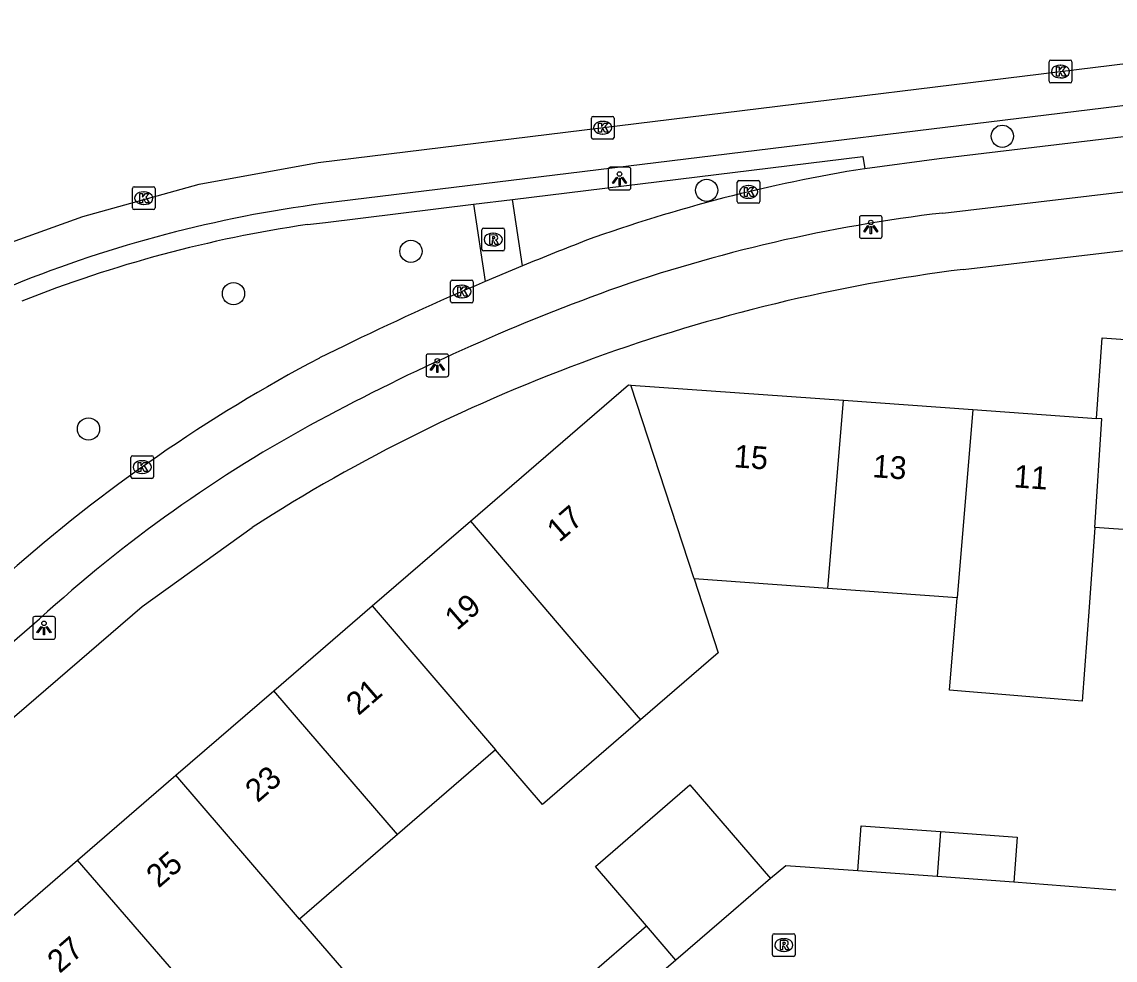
# Model space of a CAD drawing. Extents: x 160304 to 160954, y 383686 to 384161.
# Drawn here: x 160430.67 to 160478.74, y 384109.32 to 384150.58 of the extents above; entities that cross this region are included whole.
import ezdxf

# ---------------------------------------------------------------- set-up
doc = ezdxf.new("R2010")
doc.units = 0
for name, color, linetype in [('IMGEO_Berm_open', 7, 'Continuous'), ('IMGEO_Boom', 7, 'Continuous'), ('IMGEO_Fietspad_open', 7, 'Continuous'), ('IMGEO_Kolk', 7, 'Continuous'), ('IMGEO_Lichtpunt', 7, 'Continuous'), ('IMGEO_Pand', 7, 'Continuous'), ('IMGEO_Pand_nummerreeks', 7, 'Continuous'), ('IMGEO_Parkeervlak_open', 7, 'Continuous'), ('IMGEO_Rijbaan_lokaal_gesloten', 7, 'Continuous'), ('IMGEO_Rijbaan_lokaal_open', 7, 'Continuous'), ('IMGEO_Rioolput', 7, 'Continuous'), ('IMGEO_Voetpad_open', 7, 'Continuous')]:
    doc.layers.add(name, color=color, linetype=linetype)

msp = doc.modelspace()

# ---------------------------------------------------------------- linework, layer by layer
at = {"layer": 'IMGEO_Berm_open'}
for points in [[(160452.244, 384142.771), (160467.646, 384144.661), (160467.726, 384144.119)], [(160443.227, 384141.665), (160444.02, 384141.762), (160450.53, 384142.561)]]:
    msp.add_lwpolyline(points, dxfattribs=at)
msp.add_arc((160451.295, 384086.519), 55.733, 98.3238, 111.7235, dxfattribs=at)
at = {"layer": 'IMGEO_Boom'}
for centre in [(160473.778, 384145.548), (160460.776, 384143.172), (160447.773, 384140.487), (160439.974, 384138.628), (160433.596, 384132.677)]:
    msp.add_circle(centre, 0.489, dxfattribs=at)
at = {"layer": 'IMGEO_Fietspad_open'}
for points in [[(160500.935, 384148.123), (160500, 384148.012), (160470.995, 384144.557), (160467.726, 384144.119)], [(160471.168, 384142.172), (160500, 384145.577), (160501.724, 384145.785)], [(160452.675, 384139.848), (160451.032, 384139.16)], [(160444.823, 384136.323), (160443.757, 384135.797)], [(160420.593, 384114.949), (160431.449, 384124.329)]]:
    msp.add_lwpolyline(points, dxfattribs=at)
for centre, radius, start, end in [((160478.287, 384077.742), 67.212, 99.04077, 109.82387), ((160479.052, 384074.745), 67.886, 96.66896, 109.40242), ((160500.424, 384024.085), 125.224, 111.02655, 112.41499), ((160505.161, 384012.481), 137.759, 113.13674, 115.97623), ((160490.056, 384046.815), 97.892, 110.04653, 118.24507), ((160476.283, 384074.16), 69.692, 117.82068, 131.53435), ((160472.85, 384079.044), 61.358, 118.33433, 132.43502)]:
    msp.add_arc(centre, radius, start, end, dxfattribs=at)
at = {"layer": 'IMGEO_Kolk'}
for p, q in [((160475.835, 384147.967), (160475.835, 384148.819)), ((160475.91, 384148.893), (160476.762, 384148.893)), ((160476.323, 384148.673), (160476.348, 384148.673)), ((160476.836, 384148.819), (160476.836, 384147.967)), ((160476.346, 384148.113), (160476.321, 384148.113)), ((160476.762, 384147.893), (160475.91, 384147.893)), ((160455.707, 384145.496), (160455.707, 384146.348)), ((160455.782, 384146.422), (160456.634, 384146.422)), ((160456.195, 384146.202), (160456.22, 384146.202)), ((160456.708, 384146.348), (160456.708, 384145.496)), ((160456.634, 384145.422), (160455.782, 384145.422)), ((160456.218, 384145.642), (160456.193, 384145.642)), ((160435.526, 384142.399), (160435.526, 384143.251)), ((160435.601, 384143.325), (160436.453, 384143.325)), ((160436.527, 384143.251), (160436.527, 384142.399)), ((160462.121, 384142.675), (160462.121, 384143.527)), ((160462.196, 384143.601), (160463.048, 384143.601)), ((160462.609, 384143.381), (160462.634, 384143.381)), ((160463.122, 384143.527), (160463.122, 384142.675)), ((160436.014, 384143.105), (160436.039, 384143.105)), ((160462.632, 384142.821), (160462.607, 384142.821)), ((160436.453, 384142.325), (160435.601, 384142.325)), ((160436.037, 384142.545), (160436.012, 384142.545)), ((160463.048, 384142.601), (160462.196, 384142.601)), ((160449.516, 384138.295), (160449.516, 384139.147)), ((160449.591, 384139.221), (160450.443, 384139.221)), ((160450.004, 384139.001), (160450.029, 384139.001)), ((160450.517, 384139.147), (160450.517, 384138.295)), ((160450.443, 384138.221), (160449.591, 384138.221)), ((160450.027, 384138.441), (160450.002, 384138.441)), ((160435.458, 384130.574), (160435.458, 384131.426)), ((160435.533, 384131.5), (160436.385, 384131.5)), ((160435.946, 384131.28), (160435.971, 384131.28)), ((160436.459, 384131.426), (160436.459, 384130.574)), ((160436.385, 384130.5), (160435.533, 384130.5)), ((160435.969, 384130.72), (160435.944, 384130.72))]:
    msp.add_line(p, q, dxfattribs=at)
for points in [[(160475.835, 384147.967), (160475.835, 384148.819)], [(160475.91, 384148.893), (160476.762, 384148.893)], [(160476.156, 384148.593), (160476.279, 384148.593), (160476.279, 384148.442), (160476.409, 384148.593), (160476.573, 384148.593), (160476.427, 384148.442), (160476.58, 384148.193), (160476.428, 384148.193), (160476.343, 384148.357), (160476.279, 384148.29), (160476.279, 384148.193), (160476.156, 384148.193), (160476.156, 384148.593)], [(160476.836, 384148.819), (160476.836, 384147.967)], [(160476.762, 384147.893), (160475.91, 384147.893)], [(160455.707, 384145.496), (160455.707, 384146.348)], [(160455.782, 384146.422), (160456.634, 384146.422)], [(160456.708, 384146.348), (160456.708, 384145.496)], [(160456.028, 384146.122), (160456.151, 384146.122), (160456.151, 384145.971), (160456.281, 384146.122), (160456.445, 384146.122), (160456.299, 384145.971), (160456.452, 384145.722), (160456.3, 384145.722), (160456.215, 384145.886), (160456.151, 384145.819), (160456.151, 384145.722), (160456.028, 384145.722), (160456.028, 384146.122)], [(160456.634, 384145.422), (160455.782, 384145.422)], [(160435.526, 384142.399), (160435.526, 384143.251)], [(160435.601, 384143.325), (160436.453, 384143.325)], [(160436.527, 384143.251), (160436.527, 384142.399)], [(160462.121, 384142.675), (160462.121, 384143.527)], [(160462.196, 384143.601), (160463.048, 384143.601)], [(160462.442, 384143.301), (160462.565, 384143.301), (160462.565, 384143.15), (160462.695, 384143.301), (160462.859, 384143.301), (160462.713, 384143.15), (160462.866, 384142.901), (160462.714, 384142.901), (160462.629, 384143.065), (160462.565, 384142.998), (160462.565, 384142.901), (160462.442, 384142.901), (160462.442, 384143.301)], [(160463.122, 384143.527), (160463.122, 384142.675)], [(160435.847, 384143.025), (160435.97, 384143.025), (160435.97, 384142.874), (160436.1, 384143.025), (160436.264, 384143.025), (160436.118, 384142.874), (160436.271, 384142.625), (160436.119, 384142.625), (160436.034, 384142.789), (160435.97, 384142.722), (160435.97, 384142.625), (160435.847, 384142.625), (160435.847, 384143.025)], [(160436.453, 384142.325), (160435.601, 384142.325)], [(160463.048, 384142.601), (160462.196, 384142.601)], [(160449.516, 384138.295), (160449.516, 384139.147)], [(160449.591, 384139.221), (160450.443, 384139.221)], [(160450.517, 384139.147), (160450.517, 384138.295)], [(160449.837, 384138.921), (160449.96, 384138.921), (160449.96, 384138.77), (160450.09, 384138.921), (160450.254, 384138.921), (160450.108, 384138.77), (160450.261, 384138.521), (160450.109, 384138.521), (160450.024, 384138.685), (160449.96, 384138.618), (160449.96, 384138.521), (160449.837, 384138.521), (160449.837, 384138.921)], [(160450.443, 384138.221), (160449.591, 384138.221)], [(160435.458, 384130.574), (160435.458, 384131.426)], [(160435.533, 384131.5), (160436.385, 384131.5)], [(160436.459, 384131.426), (160436.459, 384130.574)], [(160435.779, 384131.2), (160435.902, 384131.2), (160435.902, 384131.049), (160436.032, 384131.2), (160436.196, 384131.2), (160436.05, 384131.049), (160436.203, 384130.8), (160436.051, 384130.8), (160435.966, 384130.964), (160435.902, 384130.897), (160435.902, 384130.8), (160435.779, 384130.8), (160435.779, 384131.2)], [(160436.385, 384130.5), (160435.533, 384130.5)]]:
    msp.add_lwpolyline(points, dxfattribs=at)
for centre, start, end in [((160475.912, 384148.817), 91.552, 178.448), ((160475.912, 384148.817), 91.552, 178.448), ((160476.76, 384148.817), 1.552, 88.448), ((160476.76, 384148.817), 1.552, 88.448), ((160475.912, 384147.969), 181.552, 268.448), ((160475.912, 384147.969), 181.552, 268.448), ((160476.76, 384147.969), 271.552, 358.448), ((160476.76, 384147.969), 271.552, 358.448), ((160455.784, 384146.346), 91.552, 178.448), ((160455.784, 384146.346), 91.552, 178.448), ((160456.632, 384146.346), 1.552, 88.448), ((160456.632, 384146.346), 1.552, 88.448), ((160455.784, 384145.498), 181.552, 268.448), ((160455.784, 384145.498), 181.552, 268.448), ((160456.632, 384145.498), 271.552, 358.448), ((160456.632, 384145.498), 271.552, 358.448), ((160435.603, 384143.249), 91.552, 178.448), ((160435.603, 384143.249), 91.552, 178.448), ((160436.451, 384143.249), 1.552, 88.448), ((160436.451, 384143.249), 1.552, 88.448), ((160462.198, 384143.525), 91.552, 178.448), ((160462.198, 384143.525), 91.552, 178.448), ((160463.046, 384143.525), 1.552, 88.448), ((160463.046, 384143.525), 1.552, 88.448), ((160435.603, 384142.401), 181.552, 268.448), ((160435.603, 384142.401), 181.552, 268.448), ((160436.451, 384142.401), 271.552, 358.448), ((160436.451, 384142.401), 271.552, 358.448), ((160462.198, 384142.677), 181.552, 268.448), ((160462.198, 384142.677), 181.552, 268.448), ((160463.046, 384142.677), 271.552, 358.448), ((160463.046, 384142.677), 271.552, 358.448), ((160449.593, 384139.145), 91.552, 178.448), ((160449.593, 384139.145), 91.552, 178.448), ((160450.441, 384139.145), 1.552, 88.448), ((160450.441, 384139.145), 1.552, 88.448), ((160449.593, 384138.297), 181.552, 268.448), ((160449.593, 384138.297), 181.552, 268.448), ((160450.441, 384138.297), 271.552, 358.448), ((160450.441, 384138.297), 271.552, 358.448), ((160435.535, 384131.424), 91.552, 178.448), ((160435.535, 384131.424), 91.552, 178.448), ((160436.383, 384131.424), 1.552, 88.448), ((160436.383, 384131.424), 1.552, 88.448), ((160435.535, 384130.576), 181.552, 268.448), ((160435.535, 384130.576), 181.552, 268.448), ((160436.383, 384130.576), 271.552, 358.448), ((160436.383, 384130.576), 271.552, 358.448)]:
    msp.add_arc(centre, 0.0765, start, end, dxfattribs=at)
for centre, major_axis, ratio, start_param, end_param in [((160476.322, 384148.393), (-0.387, 0.002), 0.722429, 4.712389, 7.853982), ((160476.347, 384148.393), (-0.39, 0.002), 0.717154, 1.570796, 4.712389), ((160456.194, 384145.922), (-0.387, 0.002), 0.722429, 4.712389, 7.853982), ((160456.219, 384145.922), (-0.39, 0.002), 0.717154, 1.570796, 4.712389), ((160462.608, 384143.101), (-0.387, 0.002), 0.722429, 4.712389, 7.853982), ((160462.633, 384143.101), (-0.39, 0.002), 0.717154, 1.570796, 4.712389), ((160436.013, 384142.825), (-0.387, 0.002), 0.722429, 4.712389, 7.853982), ((160436.038, 384142.825), (-0.39, 0.002), 0.717154, 1.570796, 4.712389), ((160450.003, 384138.721), (-0.387, 0.002), 0.722429, 4.712389, 7.853982), ((160450.028, 384138.721), (-0.39, 0.002), 0.717154, 1.570796, 4.712389), ((160435.945, 384131), (-0.387, 0.002), 0.722429, 4.712389, 7.853982), ((160435.97, 384131), (-0.39, 0.002), 0.717154, 1.570796, 4.712389)]:
    msp.add_ellipse(centre, major_axis=major_axis, ratio=ratio, start_param=start_param, end_param=end_param, dxfattribs=at)
at = {"layer": 'IMGEO_Lichtpunt'}
for p, q in [((160456.448, 384144.091), (160456.448, 384143.284)), ((160456.448, 384144.091), (160456.448, 384143.284)), ((160457.35, 384144.186), (160456.542, 384144.186)), ((160457.35, 384144.186), (160456.542, 384144.186)), ((160457.444, 384143.284), (160457.444, 384144.091)), ((160457.444, 384143.284), (160457.444, 384144.091)), ((160456.542, 384143.19), (160457.35, 384143.19)), ((160456.542, 384143.19), (160457.35, 384143.19)), ((160467.498, 384141.96), (160467.498, 384141.153)), ((160467.498, 384141.96), (160467.498, 384141.153)), ((160468.4, 384142.055), (160467.592, 384142.055)), ((160468.4, 384142.055), (160467.592, 384142.055)), ((160468.494, 384141.153), (160468.494, 384141.96)), ((160468.494, 384141.153), (160468.494, 384141.96)), ((160467.592, 384141.059), (160468.4, 384141.059)), ((160467.592, 384141.059), (160468.4, 384141.059)), ((160448.439, 384135.872), (160448.439, 384135.065)), ((160448.439, 384135.872), (160448.439, 384135.065)), ((160449.341, 384135.967), (160448.533, 384135.967)), ((160449.341, 384135.967), (160448.533, 384135.967)), ((160449.435, 384135.065), (160449.435, 384135.872)), ((160449.435, 384135.065), (160449.435, 384135.872)), ((160448.533, 384134.971), (160449.341, 384134.971)), ((160448.533, 384134.971), (160449.341, 384134.971)), ((160431.143, 384124.333), (160431.143, 384123.526)), ((160431.143, 384124.333), (160431.143, 384123.526)), ((160432.045, 384124.428), (160431.237, 384124.428)), ((160432.045, 384124.428), (160431.237, 384124.428)), ((160432.139, 384123.526), (160432.139, 384124.333)), ((160432.139, 384123.526), (160432.139, 384124.333)), ((160431.237, 384123.432), (160432.045, 384123.432)), ((160431.237, 384123.432), (160432.045, 384123.432))]:
    msp.add_line(p, q, dxfattribs=at)
for points in [[(160456.822, 384143.755), (160456.861, 384143.727), (160456.673, 384143.465), (160456.635, 384143.492), (160456.822, 384143.755)], [(160457.034, 384143.727), (160457.072, 384143.754), (160457.259, 384143.492), (160457.22, 384143.464), (160457.034, 384143.727)], [(160456.924, 384143.707), (160456.971, 384143.707), (160456.971, 384143.385), (160456.924, 384143.385), (160456.924, 384143.707)], [(160467.872, 384141.624), (160467.911, 384141.596), (160467.723, 384141.334), (160467.685, 384141.361), (160467.872, 384141.624)], [(160467.974, 384141.576), (160468.021, 384141.576), (160468.021, 384141.254), (160467.974, 384141.254), (160467.974, 384141.576)], [(160468.084, 384141.596), (160468.122, 384141.623), (160468.309, 384141.361), (160468.27, 384141.333), (160468.084, 384141.596)], [(160448.813, 384135.536), (160448.852, 384135.508), (160448.664, 384135.246), (160448.626, 384135.273), (160448.813, 384135.536)], [(160448.915, 384135.488), (160448.962, 384135.488), (160448.962, 384135.166), (160448.915, 384135.166), (160448.915, 384135.488)], [(160449.025, 384135.508), (160449.063, 384135.535), (160449.25, 384135.273), (160449.211, 384135.245), (160449.025, 384135.508)], [(160431.517, 384123.997), (160431.556, 384123.969), (160431.368, 384123.707), (160431.33, 384123.734), (160431.517, 384123.997)], [(160431.619, 384123.949), (160431.666, 384123.949), (160431.666, 384123.627), (160431.619, 384123.627), (160431.619, 384123.949)], [(160431.729, 384123.969), (160431.767, 384123.996), (160431.954, 384123.734), (160431.915, 384123.706), (160431.729, 384123.969)]]:
    msp.add_lwpolyline(points, dxfattribs=at)
for centre in [(160456.947, 384143.889), (160467.997, 384141.758), (160448.938, 384135.67), (160431.642, 384124.131)]:
    msp.add_circle(centre, 0.0994, dxfattribs=at)
for centre, start, end in [((160456.542, 384144.091), 90, 180), ((160456.542, 384144.091), 90, 180), ((160457.35, 384144.091), 0, 90), ((160457.35, 384144.091), 0, 90), ((160456.542, 384143.284), 180, 270), ((160456.542, 384143.284), 180, 270), ((160457.35, 384143.284), 270, 0), ((160457.35, 384143.284), 270, 360), ((160467.592, 384141.96), 90, 180), ((160467.592, 384141.96), 90, 180), ((160468.4, 384141.96), 0, 90), ((160468.4, 384141.96), 0, 90), ((160467.592, 384141.153), 180, 270), ((160467.592, 384141.153), 180, 270), ((160468.4, 384141.153), 270, 0), ((160468.4, 384141.153), 270, 360), ((160448.533, 384135.872), 90, 180), ((160448.533, 384135.872), 90, 180), ((160449.341, 384135.872), 0, 90), ((160449.341, 384135.872), 0, 90), ((160448.533, 384135.065), 180, 270), ((160448.533, 384135.065), 180, 270), ((160449.341, 384135.065), 270, 0), ((160449.341, 384135.065), 270, 360), ((160431.237, 384124.333), 90, 180), ((160431.237, 384124.333), 90, 180), ((160432.045, 384124.333), 0, 90), ((160432.045, 384124.333), 0, 90), ((160431.237, 384123.526), 180, 270), ((160431.237, 384123.526), 180, 270), ((160432.045, 384123.526), 270, 0), ((160432.045, 384123.526), 270, 360)]:
    msp.add_arc(centre, 0.0946, start, end, dxfattribs=at)
at = {"layer": 'IMGEO_Pand'}
for points in [[(160477.914, 384133.14), (160478.168, 384136.684), (160484.085, 384136.26)], [(160450.392, 384128.625), (160457.334, 384134.615), (160457.441, 384134.607)], [(160457.441, 384134.607), (160466.799, 384133.937)], [(160460.229, 384126.084), (160457.441, 384134.607)], [(160466.099, 384125.663), (160466.799, 384133.937)], [(160466.799, 384133.937), (160472.481, 384133.529)], [(160472.481, 384133.529), (160471.79, 384125.255)], [(160472.481, 384133.529), (160477.914, 384133.14)], [(160477.842, 384128.347), (160478.159, 384133.122), (160477.914, 384133.14)], [(160446.068, 384124.894), (160450.392, 384128.625)], [(160450.392, 384128.625), (160455.82, 384122.26), (160457.867, 384119.881)], [(160477.842, 384128.347), (160477.59, 384124.839), (160477.293, 384120.707), (160471.451, 384121.195), (160471.79, 384125.255)], [(160483.436, 384127.946), (160477.842, 384128.347)], [(160460.229, 384126.084), (160461.281, 384122.827), (160457.867, 384119.881)], [(160466.099, 384125.663), (160460.229, 384126.084)], [(160471.79, 384125.255), (160466.099, 384125.663)], [(160441.748, 384121.167), (160446.068, 384124.894)], [(160446.068, 384124.894), (160451.488, 384118.566)], [(160437.438, 384117.448), (160441.748, 384121.167)], [(160447.183, 384114.851), (160441.748, 384121.167)], [(160457.867, 384119.881), (160453.56, 384116.165), (160451.488, 384118.566)], [(160451.488, 384118.566), (160447.183, 384114.851)], [(160433.114, 384113.718), (160437.438, 384117.448)], [(160442.868, 384111.128), (160437.438, 384117.448)], [(160458.139, 384110.826), (160455.883, 384113.441), (160460.037, 384117.026), (160463.586, 384112.912)], [(160467.431, 384113.243), (160467.573, 384115.224), (160471.06, 384114.974)], [(160471.06, 384114.974), (160470.92, 384112.993)], [(160471.06, 384114.974), (160474.426, 384114.732), (160474.284, 384112.752)], [(160447.183, 384114.851), (160442.868, 384111.128)], [(160428.635, 384109.853), (160433.114, 384113.718)], [(160438.563, 384107.413), (160433.114, 384113.718)], [(160470.92, 384112.993), (160467.431, 384113.243)], [(160474.284, 384112.752), (160470.92, 384112.993)], [(160463.586, 384112.912), (160461.96, 384111.509), (160459.428, 384109.325)], [(160442.868, 384111.128), (160444.812, 384108.876), (160440.506, 384105.161), (160438.563, 384107.413)], [(160456.688, 384106.961), (160455.396, 384108.459), (160458.139, 384110.826)], [(160459.428, 384109.325), (160458.139, 384110.826)], [(160459.428, 384109.325), (160456.688, 384106.961)]]:
    msp.add_lwpolyline(points, dxfattribs=at)
at = {"layer": 'IMGEO_Parkeervlak_open'}
msp.add_lwpolyline([(160491.67, 384148.419), (160443.908, 384142.585)], dxfattribs=at)
msp.add_arc((160451.061, 384087.716), 55.333, 97.4277, 112.0391, dxfattribs=at)
at = {"layer": 'IMGEO_Rijbaan_lokaal_gesloten'}
msp.add_lwpolyline([(160416.214, 384133.836), (160418.943, 384135.557), (160423.299, 384137.892), (160429.619, 384140.679), (160433.342, 384142.025), (160438.466, 384143.437), (160443.695, 384144.386), (160494.126, 384150.577)], dxfattribs=at)
at = {"layer": 'IMGEO_Rijbaan_lokaal_open'}
for points in [[(160467.431, 384113.243), (160464.253, 384113.464), (160463.586, 384112.912)], [(160478.766, 384112.396), (160474.284, 384112.752)]]:
    msp.add_lwpolyline(points, dxfattribs=at)
at = {"layer": 'IMGEO_Rioolput'}
for p, q in [((160450.893, 384140.58), (160450.893, 384141.432)), ((160450.968, 384141.506), (160451.82, 384141.506)), ((160451.894, 384141.432), (160451.894, 384140.58)), ((160451.381, 384141.286), (160451.406, 384141.286)), ((160451.82, 384140.506), (160450.968, 384140.506)), ((160451.404, 384140.726), (160451.379, 384140.726)), ((160463.67, 384109.557), (160463.67, 384110.409)), ((160463.745, 384110.483), (160464.597, 384110.483)), ((160464.158, 384110.263), (160464.183, 384110.263)), ((160464.671, 384110.409), (160464.671, 384109.557)), ((160464.181, 384109.703), (160464.156, 384109.703)), ((160464.597, 384109.483), (160463.745, 384109.483))]:
    msp.add_line(p, q, dxfattribs=at)
for points in [[(160450.893, 384140.58), (160450.893, 384141.432)], [(160450.968, 384141.506), (160451.82, 384141.506)], [(160451.894, 384141.432), (160451.894, 384140.58)], [(160451.482, 384141.204), (160451.23, 384141.206), (160451.23, 384140.806)], [(160451.23, 384140.806), (160451.354, 384140.806), (160451.354, 384140.968), (160451.365, 384140.968)], [(160451.408, 384141.125), (160451.354, 384141.125), (160451.354, 384141.044)], [(160451.354, 384141.044), (160451.406, 384141.044)], [(160451.412, 384140.939), (160451.483, 384140.806), (160451.623, 384140.806), (160451.558, 384140.932)], [(160451.82, 384140.506), (160450.968, 384140.506)], [(160463.67, 384109.557), (160463.67, 384110.409)], [(160463.745, 384110.483), (160464.597, 384110.483)], [(160464.259, 384110.181), (160464.007, 384110.183), (160464.007, 384109.783)], [(160464.185, 384110.102), (160464.131, 384110.102), (160464.131, 384110.021)], [(160464.671, 384110.409), (160464.671, 384109.557)], [(160464.007, 384109.783), (160464.131, 384109.783), (160464.131, 384109.945), (160464.142, 384109.945)], [(160464.131, 384110.021), (160464.183, 384110.021)], [(160464.189, 384109.916), (160464.26, 384109.783), (160464.4, 384109.783), (160464.335, 384109.909)], [(160464.597, 384109.483), (160463.745, 384109.483)]]:
    msp.add_lwpolyline(points, dxfattribs=at)
for centre, radius, start, end in [((160450.97, 384141.43), 0.0765, 91.552, 178.448), ((160450.97, 384141.43), 0.0765, 91.552, 178.448), ((160451.818, 384141.43), 0.0765, 1.552, 88.448), ((160451.818, 384141.43), 0.0765, 1.552, 88.448), ((160451.364, 384140.915), 0.0533, 26.0293, 88.6989), ((160451.39, 384141.233), 0.19, 274.7715, 282.9687), ((160451.414, 384141.029), 0.0964, 77.0061, 93.1865), ((160451.428, 384141.086), 0.0378, 276.6634, 79.6772), ((160451.481, 384141.094), 0.109, 350.3612, 89.416), ((160451.479, 384141.094), 0.112, 277.5842, 350.9817), ((160451.463, 384140.879), 0.108, 29.5134, 73.7905), ((160450.97, 384140.582), 0.0765, 181.552, 268.448), ((160450.97, 384140.582), 0.0765, 181.552, 268.448), ((160451.818, 384140.582), 0.0765, 271.552, 358.448), ((160451.818, 384140.582), 0.0765, 271.552, 358.448), ((160463.747, 384110.407), 0.0765, 91.552, 178.448), ((160463.747, 384110.407), 0.0765, 91.552, 178.448), ((160464.191, 384110.006), 0.0964, 77.0061, 93.1865), ((160464.205, 384110.063), 0.0378, 276.6634, 79.6772), ((160464.258, 384110.071), 0.109, 350.3612, 89.416), ((160464.595, 384110.407), 0.0765, 1.552, 88.448), ((160464.595, 384110.407), 0.0765, 1.552, 88.448), ((160464.141, 384109.892), 0.0533, 26.0293, 88.6989), ((160464.167, 384110.21), 0.19, 274.7715, 282.9687), ((160464.256, 384110.071), 0.112, 277.5842, 350.9817), ((160464.24, 384109.856), 0.108, 29.5134, 73.7905), ((160463.747, 384109.559), 0.0765, 181.552, 268.448), ((160463.747, 384109.559), 0.0765, 181.552, 268.448), ((160464.595, 384109.559), 0.0765, 271.552, 358.448), ((160464.595, 384109.559), 0.0765, 271.552, 358.448)]:
    msp.add_arc(centre, radius, start, end, dxfattribs=at)
for centre, major_axis, ratio, start_param, end_param in [((160451.38, 384141.006), (-0.387, 0.002), 0.722429, 4.712389, 7.853982), ((160451.405, 384141.006), (-0.39, 0.002), 0.717154, 1.570796, 4.712389), ((160464.157, 384109.983), (-0.387, 0.002), 0.722429, 4.712389, 7.853982), ((160464.182, 384109.983), (-0.39, 0.002), 0.717154, 1.570796, 4.712389)]:
    msp.add_ellipse(centre, major_axis=major_axis, ratio=ratio, start_param=start_param, end_param=end_param, dxfattribs=at)
at = {"layer": 'IMGEO_Voetpad_open'}
for points in [[(160450.53, 384142.561), (160452.244, 384142.771)], [(160452.675, 384139.848), (160452.244, 384142.771)], [(160472.055, 384139.693), (160500, 384142.979), (160500.36, 384143.021)], [(160450.53, 384142.561), (160451.032, 384139.16)], [(160424.295, 384114.831), (160435.961, 384124.871), (160440.787, 384128.344)]]:
    msp.add_lwpolyline(points, dxfattribs=at)
msp.add_arc((160481.427, 384065.123), 75.157, 97.16362, 122.73401, dxfattribs=at)

# ---------------------------------------------------------------- texts
at = {"layer": 'IMGEO_Pand_nummerreeks'}
for s, rotation, p in [('15', 355.9005, (160461.954, 384130.995)), ('13', 355.9005, (160468.049, 384130.558)), ('11', 355.9034, (160474.258, 384130.113)), ('17', 40.7882, (160454.297, 384127.661)), ('19', 40.7882, (160449.803, 384123.783)), ('21', 40.7882, (160445.467, 384120.044)), ('23', 40.7882, (160441.031, 384116.215)), ('25', 40.7882, (160436.68, 384112.461)), ('27', 40.7889, (160432.328, 384108.707))]:
    msp.add_text(s, height=1, rotation=rotation, dxfattribs=at).set_placement(p)

doc.saveas('drawing.dxf')
